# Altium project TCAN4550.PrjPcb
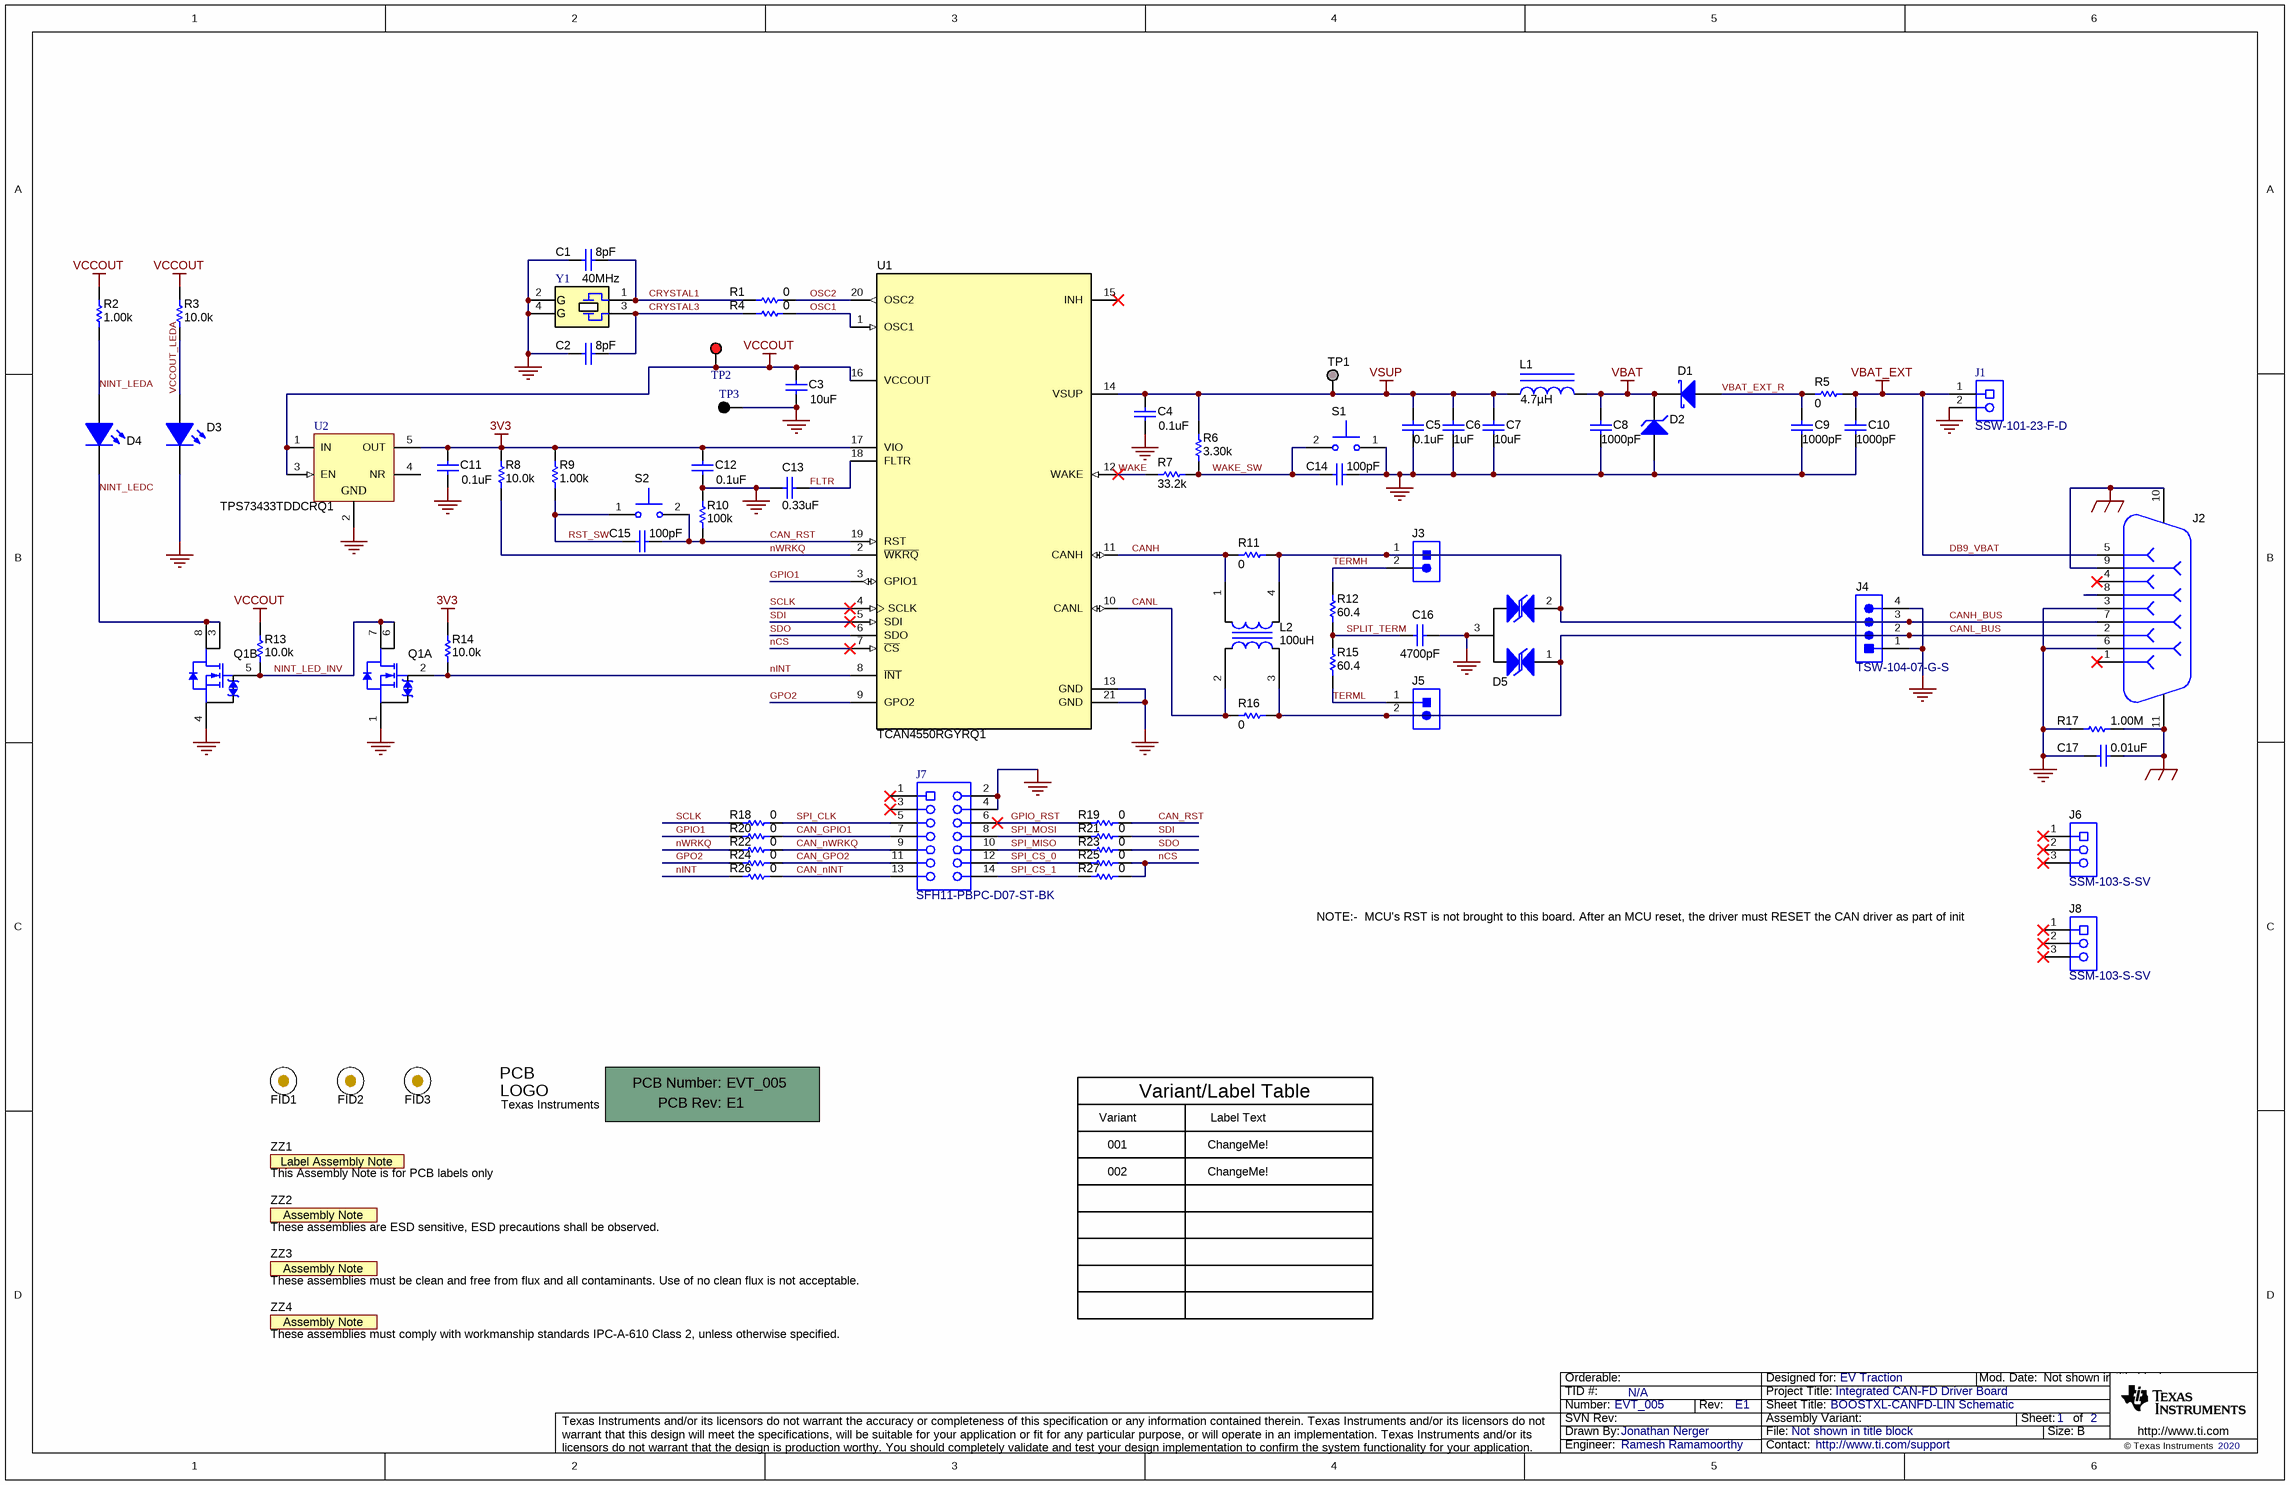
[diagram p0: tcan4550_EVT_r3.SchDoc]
CopyrightYear: 2020; PCB_Layout: Ramesh Ramamoorthy; PCB_Rev: E1; PRJ_Customer: EV Traction; PRJ_Engineer: Ramesh Ramamoorthy; PRJ_Number: EVT_005; PRJ_Title: Integrated CAN-FD Driver Board; SCH_Rev: E1; TechSupport: http://www.ti.com/support; TID: N/A
1 sheet, 77 parts. Net scope: global (net labels, ports and power ports of the same name join across sheets).
Board file: TCAN4550_r3.PcbDoc

## Sheet tcan4550_EVT_r3.SchDoc: BOOSTXL-CANFD-LIN Schematic
size 431 x 279 mm; Date: Not shown in title block; ApprovedBy: Not shown in title block; CheckedBy: Not shown in title block; Author: Not shown in title block; CompanyName: Texas Instruments; DrawnBy: Jonathan Nerger; Engineer: Jonathan Nerger; Organization: Texas Instruments; Address1: Not shown in title block; Address2: Not shown in title block; Address3: Not shown in title block; Address4: Not shown in title block; DocumentNumber: 1; Revision: Use project parameter SCH_Rev; SheetNumber: 1; SheetTotal: 2; PageSetup: Record=PageOptions¦CenterHorizontal=True¦CenterVertical=True¦PrintScale=1.00¦XCorrection=1.00¦YCorrection=1.00¦PrintKind=0¦BorderSize=5000000¦LeftOffset=0¦BottomOffset=0¦Orientation=2¦PaperLength=1000¦PaperWidth=1000¦Scale=100¦PaperSource=15¦PrintQuality=600¦MediaType=1¦DitherType=10¦PaperKind=Letter¦PrintScaleMode=1

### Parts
!PCB1  Printed Circuit Board  (value not drawn)  (mechanical)
C1  ValueDisplayed: 8pF  [0402S]  (hidden comment: CC0402DRNPO9BN8R0)
C2  ValueDisplayed: 8pF  [0402S]  (hidden comment: CC0402DRNPO9BN8R0)
C3  ValueDisplayed: 10uF  [0805]  (hidden comment: CL21B106KOQNNNE)
C4  ValueDisplayed: 0.1uF  [0603S]  (hidden comment: CGA3E2X7R1H104K080AA)
C5  ValueDisplayed: 0.1uF  [0603S]  (hidden comment: CGA3E2X7R1H104K080AA)
C6  ValueDisplayed: 1uF  [0603S]  (hidden comment: UMK107AB7105KA-T)
C7  ValueDisplayed: 10uF  [1206_180]  (hidden comment: CL31B106KBHNNNE)
C8  ValueDisplayed: 1000pF  [0603S]  (hidden comment: CGA3E2X7R2A102K080AA)
C9  ValueDisplayed: 1000pF  [0603S]  (hidden comment: CGA3E2X7R2A102K080AA)
C10  ValueDisplayed: 1000pF  [0603S]  (hidden comment: CGA3E2X7R2A102K080AA)
C11  ValueDisplayed: 0.1uF  [0603S]  (hidden comment: CGA3E2X7R1H104K080AA)
C12  ValueDisplayed: 0.1uF  [0603S]  (hidden comment: CGA3E2X7R1H104K080AA)
C13  ValueDisplayed: 0.33uF  [0603S]  (hidden comment: C0603C334K4RACTU)
C14  ValueDisplayed: 100pF  [0603S]  (hidden comment: 06035A101JAT2A)
C15  ValueDisplayed: 100pF  [0603S]  (hidden comment: 06035A101JAT2A)
C16  ValueDisplayed: 4700pF  [0603]  (hidden comment: 06031C472KAT2A)
C17  ValueDisplayed: 0.01uF  [1206]  (hidden comment: 12061C103JAT2A)
D1  MBRA140T3G  [SMA]  (value not drawn)
D2  3SMAJ5936B-TP  [SMA]  (value not drawn)
D3  150060GS75000  [WL-SMCW_GREEN]  (value not drawn)
D4  150060BS75000  [WL-SMCW_Blue]  (value not drawn)
D5  PESD1CAN,215  [SOT-23]  (value not drawn)
FID1  Fiducial  [Fiducial10-20]  (value not drawn)
FID2  Fiducial  [Fiducial10-20]  (value not drawn)
FID3  Fiducial  [Fiducial10-20]  (value not drawn)
J1  SSW-101-23-F-D  [Samtec_SSW-101-23-x-D]
J2  5747840-5  [TE_5747840-5]  (value not drawn)
J3  TSW-102-07-G-S  [TSW-102-07-G-S]  (value not drawn)
J4  TSW-104-07-G-S  [TSW-104-07-G-S]
J5  TSW-102-07-G-S  [TSW-102-07-G-S]  (value not drawn)
J6  SSM-103-S-SV  [Samtec_SSM-103-x-SV]
J7  SFH11-PBPC-D07-ST-BK  [Sullins_SFH11-xxxC-D07-ST-BK]
J8  SSM-103-S-SV  [Samtec_SSM-103-x-SV]
L1  ValueDisplayed: 4.7µH  [B82462A4]  (hidden comment: B82462A4472M000)
L2  ValueDisplayed: 100uH  [ACT45B]  (hidden comment: ACT45B-101-2P-TL003)
Logo1  Texas Instruments  [TI_Symbol_Overlay_Small]  (no BOM)
Q1  CSD85301Q2  [DQK0006B]  (value not drawn)  (parts A,B of 2)
R1  ValueDisplayed: 0  [0402S]  (hidden comment: RC0402JR-070RL)
R2  ValueDisplayed: 1.00k  [0402S]  (hidden comment: RC0402FR-071KL)
R3  ValueDisplayed: 10.0k  [0402S]  (hidden comment: RC0402FR-0710KL)
R4  ValueDisplayed: 0  [0402S]  (hidden comment: RC0402JR-070RL)
R5  ValueDisplayed: 0  [5106]  (hidden comment: 5106)
R6  ValueDisplayed: 3.30k  [0402S]  (hidden comment: ERJ-2RKF3301X)
R7  ValueDisplayed: 33.2k  [0402S]  (hidden comment: CRCW040233K2FKED)
R8  ValueDisplayed: 10.0k  [0402S]  (hidden comment: RC0402FR-0710KL)
R9  ValueDisplayed: 1.00k  [0402S]  (hidden comment: RC0402FR-071KL)
R10  ValueDisplayed: 100k  [0402S]  (hidden comment: RC1005F104CS)
R11  ValueDisplayed: 0  [1206]  (hidden comment: ERJ-8GEY0R00V)
R12  ValueDisplayed: 60.4  [0603]  (hidden comment: RC0603FR-0760R4L)
R13  ValueDisplayed: 10.0k  [0402S]  (hidden comment: RC0402FR-0710KL)
R14  ValueDisplayed: 10.0k  [0402S]  (hidden comment: RC0402FR-0710KL)
R15  ValueDisplayed: 60.4  [0603]  (hidden comment: RC0603FR-0760R4L)
R16  ValueDisplayed: 0  [1206]  (hidden comment: ERJ-8GEY0R00V)
R17  ValueDisplayed: 1.00M  [0402S]  (hidden comment: ERJ-2RKF1004X)
R18  ValueDisplayed: 0  [0402S]  (hidden comment: RC0402JR-070RL)
R19  ValueDisplayed: 0  [0402S]  (hidden comment: RC0402JR-070RL)
R20  ValueDisplayed: 0  [0402S]  (hidden comment: RC0402JR-070RL)
R21  ValueDisplayed: 0  [0402S]  (hidden comment: RC0402JR-070RL)
R22  ValueDisplayed: 0  [0402S]  (hidden comment: RC0402JR-070RL)
R23  ValueDisplayed: 0  [0402S]  (hidden comment: RC0402JR-070RL)
R24  ValueDisplayed: 0  [0402S]  (hidden comment: RC0402JR-070RL)
R25  ValueDisplayed: 0  [0402S]  (hidden comment: RC0402JR-070RL)
R26  ValueDisplayed: 0  [0402S]  (hidden comment: RC0402JR-070RL)
R27  ValueDisplayed: 0  [0402S]  (hidden comment: RC0402JR-070RL)
S1  B3U-1000P  [SW_B3U-1000P]  (value not drawn)
S2  B3U-1000P  [SW_B3U-1000P]  (value not drawn)
TP1  TP_SM_1MM  [TP_SM_1MM]  (value not drawn)  (no BOM)
TP2  5010  [Keystone5010]  (value not drawn)
TP3  5011  [Keystone5011]  (value not drawn)
U1  TCAN4550RGYRQ1  [RGY0020C]
U2  TPS73433TDDCRQ1  [DDC0005A_N]
Y1  Frequency_Fixed: 40MHz  [XTAL_NX2016SA]  (hidden comment: NX2016SA-40M-STD-CZS-3)
ZZ1  This Assembly Note is for PCB labels only  [AssemblyNoteLabel]  (no BOM)
ZZ2  These assemblies are ESD sensitive, ESD precautions shall be observed.  [AssemblyNote]  (no BOM)
ZZ3  These assemblies must be clean and free from flux and all contaminants. Use of no clean flux is not acceptable.  [AssemblyNote]  (no BOM)
ZZ4  These assemblies must comply with workmanship standards IPC-A-610 Class 2, unless otherwise specified.  [AssemblyNote]  (no BOM)

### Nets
3V3: C11.1 C12.1 R8.2 R9.2 R14.2 U1.17(VIO) U2.5(OUT)
DB9_VBAT: C10.1 J1.1 J2.5 R5.2  [also labelled VBAT_EXT]
GND: C1.2 C2.2 C3.2 C4.2 C5.2 C6.2 C7.2 C8.2 C9.2 C10.2 C11.2 C12.2 C13.2 C14.2 C16.1 C17.2 D2.2(A) D3.1(K) D5.3 J1.2 J2.3 J2.6 J4.1 J4.4 J7.2 J7.4 Q1.1(S1) Q1.4(S2) R10.1 R17.1 S1.1 TP3.1 U1.13(GND) U1.21(GND) U2.2(GND) Y1.2(GND) Y1.4(GND)
SHIELD_GND: C17.1 J2.9 J2.10 J2.11 R17.2
VBAT: C8.1 D1.1(K) D2.1(K) L1.2
VCCOUT: C3.1 R2.2 R3.2 R13.2 TP2.1 U1.16(VCCOUT) U2.1(IN) U2.3(EN)
VSUP: C4.1 C5.1 C6.1 C7.1 L1.1 R6.2 TP1.1 U1.14(VSUP)
CAN_GPIO1: J7.7 R20.2
CAN_GPO2: J7.11 R24.2
CAN_nINT: J7.13 R26.2
CAN_nWRKQ: J7.9 R22.2
CAN_RST: C15.1 R10.2 R19.2 S2.2 U1.19(RST)
CANH: L2.1 R11.1 U1.11(CANH)
CANH_BUS: D5.2 J2.7 J3.1 J4.3 L2.4 R11.2
CANL: L2.2 R16.1 U1.10(CANL)
CANL_BUS: D5.1 J2.2 J4.2 J5.2 L2.3 R16.2
CRYSTAL1: C1.1 R1.2 Y1.1
CRYSTAL3: C2.1 R4.2 Y1.3
FLTR: C13.1 U1.18(FLTR)
GPIO1: R20.1 U1.3(GPIO1)
GPIO_RST: J7.6 R19.1
GPO2: R24.1 U1.9(GPO2)
nCS: R25.2 R27.2 U1.7(~{CS})
nINT: Q1.2(G1) R14.1 R26.1 U1.8(~{INT})
NINT_LED_INV: Q1.5(G2) Q1.6(D1) Q1.7(D1) R13.1
NINT_LEDA: D4.2(A) R2.1
NINT_LEDC: D4.1(K) Q1.3(D2) Q1.8(D2)
nWRKQ: R8.1 R22.1 U1.2(~{WKRQ})
OSC1: R4.1 U1.1(OSC1)
OSC2: R1.1 U1.20(OSC2)
RST_SW: C15.2 R9.1 S2.1
SCLK: R18.1 U1.4(SCLK)
SDI: R21.2 U1.5(SDI)
SDO: R23.2 U1.6(SDO)
SPI_CLK: J7.5 R18.2
SPI_CS_0: J7.12 R25.1
SPI_CS_1: J7.14 R27.1
SPI_MISO: J7.10 R23.1
SPI_MOSI: J7.8 R21.1
SPLIT_TERM: C16.2 R12.1 R15.2
TERMH: J3.2 R12.2
TERML: J5.1 R15.1
VBAT_EXT_R: C9.1 D1.2(A) R5.1
VCCOUT_LEDA: D3.2(A) R3.1
WAKE: R7.2 U1.12(WAKE)
WAKE_SW: C14.1 R6.1 R7.1 S1.2

Not connected (* = marked no-connect by the designer): J2 1* 4* 8; J6 1* 2* 3*; J7 1* 3*; J8 1* 2* 3*; U1 15(INH)*; U2 4(NR)

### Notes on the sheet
- NOTE:-  MCU's RST is not brought to this board. After an MCU reset, the driver must RESET the CAN driver as part of init
- Variant/Label Table
- Variant
- 001
- 002
- Label Text
- ChangeMe!

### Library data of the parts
!PCB1 = CMP-0003618-2: Manufacturer: Any; PartNumber: EVT_005
C1 C2 = CMP-0860185-1: CAP, CERM, 8 pF, 50 V,+/- 6.25%, C0G/NP0, 0402; Manufacturer: Yageo; TaMin_C: -55°C; Polarized: N; SizeAreaWB_mm2: 3; U/M: EA; Value: 8pF; TaMax_C: 125°C; SizeZ_mm: 0.6; SizeX_mm: 1; SizeY_mm: 0.5; Cap_Case: 0402; Value2: 50V; AEC Category: Q200
C3 = CMP-0007995-2: CAP, CERM, 10 uF, 16 V, +/- 10%, X7R, 0805; Manufacturer: Samsung Electro-Mechanics; TaMin_C: -55°C; Polarized: N; SizeAreaWB_mm2: 6.75; Value1: Unknown; U/M: EA; Value: 10uF; TaMax_C: 125°C; SizeZ_mm: 1.45; SizeX_mm: 2; SizeY_mm: 1.25; Value2: 16V; SizeArea_mm2: 2.5; Cap_F: 10µF; AEC Category: Q200
C4 C5 C11 C12 = CMP-0007078-4: CAP, CERM, 0.1 uF, 50 V, +/- 10%, X7R, AEC-Q200 Grade 1, 0603; Manufacturer: TDK; TaMin_C: -55°C; ESR_ohm: 0.0296; Polarized: N; SizeAreaWB_mm2: 4.68; Value1: 0.0296 ohm; U/M: EA; Value: 0.1uF; TaMax_C: 125°C; SizeZ_mm: 1; SizeX_mm: 1.6; SizeY_mm: 0.8; Cap_Case: 0603; Value2: 50V; SizeArea_mm2: 1.28; AEC Qualified: Y; Cap_F: 100nF; IRMS_A: 971.99mA; AEC Category: Q200
C6 = CMP-0007508-5: CAP, CERM, 1 uF, 50 V, +/- 10%, X7R, 0603; Manufacturer: Taiyo Yuden; TaMin_C: -55°C; Polarized: N; SizeAreaWB_mm2: 4.68; Value1: Unknown; U/M: EA; Value: 1uF; TaMax_C: 125°C; SizeZ_mm: 1; SizeX_mm: 1.6; SizeY_mm: 0.8; Cap_Case: 0603; Value2: 50V; SizeArea_mm2: 1.28; Cap_F: 1µF; AEC Category: Q200
C7 = CMP-0008802-2: CAP, CERM, 10 uF, 50 V, +/- 10%, X7R, 1206; Manufacturer: Samsung; TaMin_C: -55°C; Polarized: N; SizeAreaWB_mm2: 10.92; Value1: Unknown; U/M: EA; Value: 10uF; TaMax_C: 125°C; SizeZ_mm: 1.8; SizeX_mm: 3.2; SizeY_mm: 1.6; Cap_Case: 1206; Value2: 50V; SizeArea_mm2: 5.12; Cap_F: 10µF; AEC Category: Q200
C8-C10 = CMP-0007081-4: CAP, CERM, 1000 pF, 100 V, +/- 10%, X7R, AEC-Q200 Grade 1, 0603; Manufacturer: TDK; TaMin_C: -55°C; Polarized: N; SizeAreaWB_mm2: 4.68; Value1: 1.97137 ohm; U/M: EA; Value: 1000pF; TaMax_C: 125°C; SizeZ_mm: 1; SizeX_mm: 1.6; SizeY_mm: 0.8; Cap_Case: 0603; Value2: 100V; SizeArea_mm2: 1.28; AEC Qualified: Y; Cap_F: 1nF; AEC Category: Q200; ESR_ohm: 1.97137; IRMS_A: 305.705mA
C13 = CMP-0006924-4: CAP, CERM, 0.33 uF, 16 V, +/- 10%, X7R, 0603; Manufacturer: Kemet; TaMin_C: -55°C; Polarized: N; SizeAreaWB_mm2: 4.68; Value1: Unknown; U/M: EA; Value: 0.33uF; TaMax_C: 125°C; SizeZ_mm: 1; SizeX_mm: 1.6; SizeY_mm: 0.8; Cap_Case: 0603; Value2: 16V; SizeArea_mm2: 1.28; Cap_F: 330nF; AEC Category: Q200
C14 C15 = CMP-0006763-4: CAP, CERM, 100 pF, 50 V, +/- 5%, C0G/NP0, 0603; Manufacturer: AVX; TaMin_C: -55°C; ESR_ohm: 1.19d; Polarized: N; SizeAreaWB_mm2: 4.68; Value1: 0.119 ohm; U/M: EA; Value: 100pF; TaMax_C: 125°C; SizeZ_mm: 1; SizeX_mm: 1.6; SizeY_mm: 0.8; Cap_Case: 0603; Value2: 50V; SizeArea_mm2: 1.28; AEC Category: Q200
C16 = CMP-0006746-5: CAP, CERM, 4700 pF, 100 V, +/- 10%, X7R, 0603; Manufacturer: AVX; TaMin_C: -55°C; ESR_ohm: 1.36d; Polarized: N; SizeAreaWB_mm2: 4.68; Value1: 0.136 ohm; U/M: EA; Value: 4700pF; TaMax_C: 125°C; SizeZ_mm: 1; SizeX_mm: 1.6; SizeY_mm: 0.8; Value2: 100V; SizeArea_mm2: 1.28; Cap_F: 4.7nF; AEC Category: Q200
C17 = CMP-0008484-2: CAP, CERM, 0.01 uF, 100 V, +/- 5%, X7R, 1206; Manufacturer: AVX; TaMin_C: -55°C; ESR_ohm: 1.19d; Polarized: N; SizeAreaWB_mm2: 10.92; Value1: 0.119 ohm; U/M: EA; Value: 0.01uF; TaMax_C: 125°C; SizeZ_mm: 1.35; SizeX_mm: 3.2; SizeY_mm: 1.6; Value2: 100V; SizeArea_mm2: 5.12; Cap_F: 10nF; AEC Category: Q200
D1 = CMP-0028550-2: Diode, Schottky, 40 V, 1 A, SMA; Manufacturer: ON Semiconductor; Io_A: 1A; Green_Lifecycle: Not Set; SizeAreaWB_mm2: 37.3428; Vr_V: 40V; Green_REACh: Incomplete; TJmax_C: 125°C; Value: 40V; SizeZ_mm: 2.87; SizeX_mm: 5.59; SizeY_mm: 2.92; Vf_V: 550mV; Value2: 0.55V; SizeArea_mm2: 16.3228; AEC Category: Q101; RJC_CperW: 35
D2 = CMP-0005515-4: Diode, Zener, 30 V, 3 W, SMA; Manufacturer: Micro Commercial Components; Power_W: 3W; SizeAreaWB_mm2: 37.3428; Vz_V: 30V; RJA_CperW: 226; Value: 30V; SizeZ_mm: 2.87; SizeX_mm: 5.59; SizeY_mm: 2.92; SizeArea_mm2: 16.3228; AEC Category: Q101
D3 = CMP-0002905-2: LED, Green, SMD; Manufacturer: Wurth Elektronik; Io_A: 20mA; Tjmax_C: 85°C; Value1: W; Angle: 140; Vf_V: 3.2V; Type: InGaN
D4 = CMP-0002946-3: LED, Blue, SMD; Manufacturer: Wurth Elektronik; Io_A: 30mA; Value1: 0.105W; Vf_V: 3.2V; Type: InGaN; Angle: 140; Power_TotalModule: 105mW; Tjmax_C: 85°C; Vr_V: 5V
D5 = CMP-0005920-3: Diode, TVS, Bi, 24 V, 70 Vc, AEC-Q101, SOT-23; Manufacturer: NXP Semiconductor; SizeAreaWB_mm2: 14; Value1: 200W; Value: 24V; SizeZ_mm: 1.1; SizeX_mm: 2.5; SizeY_mm: 3; SizeArea_mm2: 7.5; AEC Qualified: Y; AEC Category: Q101; Ipp: 3A; Vbr_Max: 30.3V; Vbr_Min: 25.4V; Vc: 70V
FID1-FID3 = CMP-0077181-1: Fiducial mark.  There is nothing to buy or mount.
J1 = CMP-0055671-1: Receptacle, 2.54mm, 1x2, Gold, TH; Manufacturer: Samtec; CNHeader: FALSE; Current_A: 5.7A; Gender: Female; Cert_CSA: Y; Voltage_V: 550V; CompType: Socket Strip; Row_Count: 2; RowSpacing_mm: 2.54; CT: TRUE
J2 = CMP-0054938-4: D-Sub, 2.74mm, 9 Position, R/A, TH; Manufacturer: TE Connectivity; CNHeader: FALSE; Gender: Male; Row_Count: 2; Pitch_mm: 2.74; ContactFinish: Gold; CT: TRUE; Cert_UL: Y
J3 J5 = CMP-0075405-2: Header, 100mil, 2x1, Gold, TH; Manufacturer: Samtec; Pitch_mm: 2.54; Gender: Male; Cert_CSA: Y; Row_Count: 1; Cert_CULUS: N; Current_A: 6.3A; Green_Lifecycle: Active; Green_REACh: Passed; Voltage_V: 550V
J4 = CMP-0075409-2: Header, 100mil, 4x1, Gold, TH; Manufacturer: Samtec; Pitch_mm: 2.54; Cert_VDE: N; Gender: Male; Cert_CSA: Y; Voltage_V: 550V; Green_REACh: Passed; Current_A: 6.3A; Green_Lifecycle: Active; Row_Count: 1
J6 J8 = CMP-0078183-1: Receptacle, 2.54mm, 3x1, Gold with Tin tail, SMT; Manufacturer: Samtec; Pitch_mm: 2.54; Gender: Female; Cert_CSA: Y; Voltage_V: 405V; Current_A: 5.2A; Row_Count: 1; CompType: Socket Strip
J7 = CMP-0054668-1: Receptacle, 2.54mm, 7x2, Gold, Black, TH; Manufacturer: Sullins Connector Solutions; CNHeader: FALSE; Current_A: 3A; Gender: Female; Voltage_V: 1kV; CompType: Socket Strip; Row_Count: 2; RowSpacing_mm: 2.54; CT: TRUE; Cert_UL: Y
L1 = CMP-0001617-1: Inductor, Wirewound, Ferrite, 4.7 µH, 1.65 A, 0.08 ohm, AEC-Q200 Grade 0, SMD; Manufacturer: TDK; Isat: 2.8A @ 10% inductance drop; Irms: 1.65A @ 40C rise; SizeAreaWB_mm2: 64.0; DCR_ohm: 0.08; Value: 4.7uH; Imax_A: 1.65A; SizeZ_mm: 3.0; SizeX_mm: 6.0; SizeArea_mm2: 36.0; AEC Qualified: Y; AEC Grade: 0; AEC Category: Q200
L2 = CMP-0062430-2: Inductor, Ferrite, 100 uH, 0.15 A, 2 ohm, SMD; Manufacturer: TDK; Isat: 0.15A @ % inductance drop; Green_Lifecycle: Active; SizeAreaWB_mm2: 23.1; DCR_ohm: 2; Green_REACh: Passed; Value1: 2 ohm; Value: 100uH; Imax_A: 1.5dA; SizeZ_mm: 3; SizeX_mm: 4.5; SizeY_mm: 3.2; Value2: 0.15A; SizeArea_mm2: 14.4; Ind_H: 100µH; AEC Category: Q200
Logo1 = CMP-0074838-1: Texas Instrument Corporate Signature; SymbolCreator: a0412235; Lib Reference: TI_Logo; Library Reference: Logo
Q1 = CMP-0000208-1: MOSFET, 2-CH, N-CH, 20 V, 6.7 A, DQK0006B (WSON-6); Alternate Manufacturer: None; Manufacturer: Texas Instruments; SizeZ_mm: 0.8; ChType: N; Value2: 4.2 nC; Value1: 0.02; VdsMax_V: 20V; SizeX_mm: 2; Vgs_V: 10V; Value: 20V; Rdson45_ohm: 0.023; SizeArea_mm2: 4; AEC Category: Q101; IdsMax_A: 6.7A; SizeAreaWB_mm2: 9; U/M: EA; QgTyp_nC: 4.2
R1 R4 R18-R27 = CMP-0027004-2: RES, 0, 5%, 0.063 W, 0402; Manufacturer: Yageo America; Power_W: 63mW; TempCo: 200 ppm/C; Value_Code: 0000; U/M: EA; Value: 0; EIA_Code: E24; SizeX_mm: 1; SizeY_mm: 0.5; SizeZ_mm: 0.6; Value2: 0.063W; VDC_V: 50V; AEC Category: Q200
R2 R9 = CMP-0026725-1: RES, 1.00 k, 1%, 0.0625 W, 0402; Manufacturer: Yageo America; Power_W: 62.5mW; TempCo: 100 ppm/C; Value_Code: 1k00; Value: 1.00k; EIA_Code: E96; Res_ohm: 1k; SizeX_mm: 1; SizeY_mm: 0.5; SizeZ_mm: 0.6; AEC Qualified: N; VDC_V: 50V; AEC Category: Q200; U/M: EA
R3 = CMP-0078669-1: RES, 10.0 k, 1%, 0.063 W, 0402; Manufacturer: Yageo America; Power_W: 63mW; TempCo: 100 ppm/C; Value_Code: 10k0; Value: 10.0k; EIA_Code: E96; Res_ohm: 10k; SizeX_mm: 1; SizeY_mm: 0.5; SizeZ_mm: 0.6; Value2: 0.063W; AEC Qualified: N; AEC Category: Q200; Green_Lifecycle: Active; Green_REACh: Passed
R5 = CMP-0020833-2: RES, 0, 1%, 0.5 W, 0805; Manufacturer: Keystone; Power_W: 500mW; TempCo: ppm/C; U/M: EA; Value: 0; SizeX_mm: 2; SizeY_mm: 1.25; SizeZ_mm: 0.84; Value2: 0.5W; SizeArea_mm2: 2.5; AEC Qualified: N; AEC Category: Q200
R6 = CMP-0026695-1: RES, 3.30 k, 1%, 0.1 W, AEC-Q200 Grade 0, 0402; Manufacturer: Panasonic; Power_W: 100mW; TempCo: 100 ppm/C; Value_Code: 3k30; U/M: EA; Value: 3.30k; Res_ohm: 3.3k; SizeX_mm: 1; SizeY_mm: 0.5; SizeZ_mm: 0.6; Value2: 0.1W; AEC Qualified: Y; VDC_V: 50V; AEC Grade: 0; AEC Category: Q200
R7 = CMP-0026298-2: RES, 33.2 k, 1%, 0.063 W, AEC-Q200 Grade 0, 0402; Manufacturer: Vishay-Dale; Power_W: 63mW; TempCo: 100 ppm/C; Value_Code: 33k2; Value: 33.2k; EIA_Code: E96; SizeX_mm: 1; SizeY_mm: 0.5; SizeZ_mm: 0.6; Value2: 0.063W; AEC Qualified: Y; VDC_V: 50V; AEC Category: Q200; AEC Grade: 0
R8 R13 R14 = CMP-0078669-1: RES, 10.0 k, 1%, 0.063 W, 0402; Manufacturer: Yageo America; Power_W: 63mW; Green_Lifecycle: Active; TempCo: 100 ppm/C; Value_Code: 10k0; Green_REACh: Passed; Value: 10.0k; EIA_Code: E96; Res_ohm: 10k; SizeX_mm: 1; SizeY_mm: 0.5; SizeZ_mm: 0.6; Value2: 0.063W; AEC Qualified: N; AEC Category: Q200
R10 = CMP-0026745-1: RES, 100 k, 1%, 0.063 W, 0402; Manufacturer: Samsung Electro-Mechanics; Power_W: 63mW; TempCo: 100 ppm/C; U/M: EA; Value: 100k; EIA_Code: E96; SizeX_mm: 1; SizeY_mm: 0.5; SizeZ_mm: 0.6; Value2: 0.063W; AEC Qualified: N; VDC_V: 80V; AEC Category: Q200
R11 R16 = CMP-0018748-3: RES, 0, 5%, 0.25 W, AEC-Q200 Grade 0, 1206; Manufacturer: Panasonic; Power_W: 250mW; TempCo: 600 ppm/C; Value_Code: 0000; Value: 0; EIA_Code: E24; SizeX_mm: 3.2; SizeY_mm: 1.6; SizeZ_mm: 1.35; Value2: 0.25W; SizeArea_mm2: 5.12; AEC Qualified: Y; VDC_V: 200V; AEC Category: Q200; SizeAreaWB_mm2: 10.92
R12 R15 = CMP-0023213-5: RES, 60.4, 1%, 0.1 W, 0603; Manufacturer: Yageo; Power_W: 100mW; TempCo: 100 ppm/C; Value_Code: 60R4; Value: 60.4; EIA_Code: E96; SizeX_mm: 1.6; SizeY_mm: 0.8; SizeZ_mm: 1; Value2: 0.1W; SizeArea_mm2: 1.28; AEC Qualified: N; VDC_V: 75V; AEC Category: Q200; SizeAreaWB_mm2: 4.68
R17 = CMP-0026660-1: RES, 1.00 M, 1%, 0.1 W, 0402; Manufacturer: Panasonic; Power_W: 100mW; TempCo: 100 ppm/C; Value_Code: 1M00; U/M: EA; Value: 1.00Meg; EIA_Code: E96; Res_ohm: 1M; SizeX_mm: 1; SizeY_mm: 0.5; SizeZ_mm: 0.6; Value2: 0.1W; VDC_V: 50V; AEC Category: Q200
S1 S2 = CMP-0002150-2: SWITCH TACTILE SPST-NO 0.05A 12V; Manufacturer: Omron Electronic Components; CurrentRating_mA: 50A; PositionCount: 1; SwitchFunction: Off-Mom
TP1 = CMP-0003825-1: 1mm Test Point, SMT; Manufacturer: Any
TP2 = CMP-0055147-1: Test Point, Multipurpose, Red, TH; Manufacturer: Keystone; CNHeader: FALSE; Green_Lifecycle: Active; Green_REACh: Passed; ContactFinish: Silver; CT: TRUE
TP3 = CMP-0055148-1: Test Point, Multipurpose, Black, TH; Manufacturer: Keystone; CNHeader: FALSE; Green_Lifecycle: Active; Green_REACh: Passed; ContactFinish: Silver; CT: TRUE
U1 = CMP-0065224-7: CAN-FD Controller with Integrated Transceiver, RGY0020A (VQFN-20); Alternate PartNumber: TCAN4550RGYQ1; Manufacturer: Texas Instruments; SizeZ_mm: 1.0; SizeX_mm: 3.5; SizeY_mm: 4.5; SizeArea_mm2: 15.75; CompType: IC; SizeAreaWB_mm2: 24.75; AEC Category: Q200; AEC Qualified: Y; Rating: Automotive
U2 = CMP-0035843-1: Single Output High PSRR LDO, 250 mA, Fixed 3.3 V Output, 2.7 to 6.5 V Input, with Low IQ, 5-pin SOT (DDC), -40 to 105 degC, Green (RoHS & no Sb/Br); Manufacturer: Texas Instruments; Rating: Automotive; Vout Adj(Max)(V): 3.3; SubFamily: Single Channel LDO; Vin(Max)(V): 6.5; Vin(Min)(V): 2.7; Accuracy(%): 2; Vdo(Typ)(mV): 125; Iq(Typ)(mA): 0.04; Iout(Max)(A): 0.2
Y1 = CMP-0085289-1: Crystal, 40 MHz, 10 ppm, 8 pF, AEC-Q200 Grade 0, SMD; Manufacturer: NDK; TaMin_C: -40°C; Frequency Stability: 25 ppm; TaMax_C: 125°C; AEC Category: Q200; AEC Grade: 0; AEC Qualified: Y; Frequency Tolerance: 10 ppm; Load Capacitance: 8 pF
ZZ1 = CMP-0003616-3
ZZ2 = CMP-0077236-1
ZZ3 = CMP-0077237-1
ZZ4 = CMP-0077238-1

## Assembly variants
001: not fitted FID1 FID2 FID3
